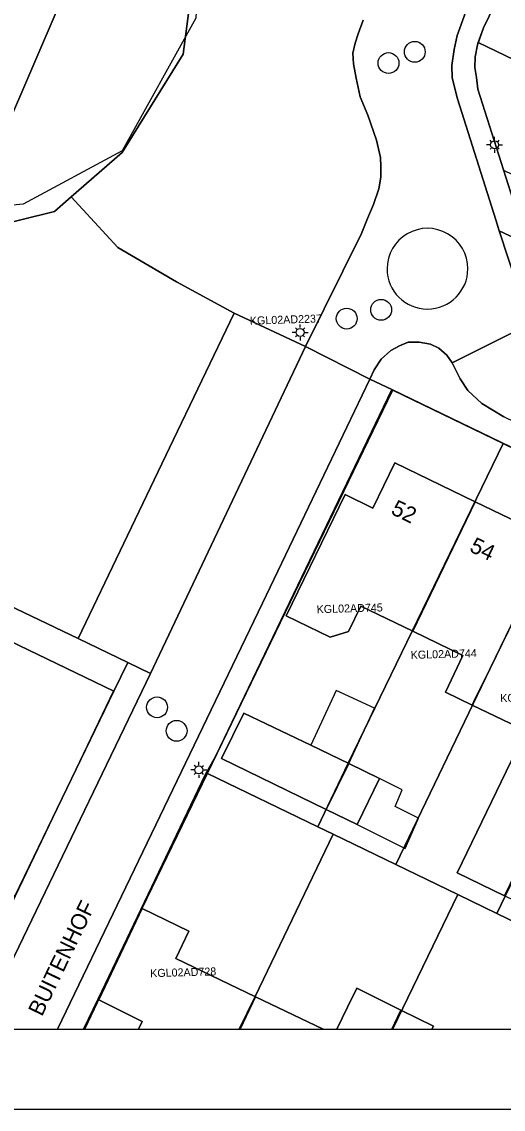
# Model space of a CAD drawing. Extents: x 124901 to 125496, y 515369 to 515789.
# Drawn here: x 125140.8 to 125170.8, y 515368.5 to 515436.5 of the extents above; entities that cross this region are included whole.
import ezdxf

# ---------------------------------------------------------------- set-up
doc = ezdxf.new("R2010")
doc.units = 0
for name, color, linetype in [('Alg Kaders', 7, 'Continuous'), ('Gebouw', 7, 'Continuous'), ('Lichtmast', 7, 'Continuous'), ('Luifel', 7, 'Continuous'), ('Onbegroeid terrein', 7, 'Continuous'), ('Parkeren', 7, 'Continuous'), ('Perceelnummers', 7, 'Continuous'), ('Perceelsgrenzen', 7, 'Continuous'), ('Putten', 7, 'Continuous'), ('Scheiding', 7, 'Continuous'), ('Teksten', 7, 'Continuous'), ('Vegetatie', 7, 'Continuous'), ('Voetpad', 7, 'Continuous'), ('Wegen drempel verkeerseiland', 7, 'Continuous'), ('Wegen lokale weg', 7, 'Continuous')]:
    doc.layers.add(name, color=color, linetype=linetype)

msp = doc.modelspace()

# ---------------------------------------------------------------- linework, layer by layer
at = {"layer": 'Alg Kaders'}
for points in [[(125495.925, 515789.043), (124901.425, 515789.043), (124901.425, 515368.543), (125495.925, 515368.543)], [(125490.925, 515784.043), (124906.425, 515784.043), (124906.425, 515373.543), (125490.925, 515373.543)]]:
    msp.add_lwpolyline(points, close=True, dxfattribs=at)
at = {"layer": 'Gebouw'}
for points in [[(125165.169, 515398.421), (125169.07, 515406.51), (125164.06, 515408.94), (125162.687, 515406.107), (125160.95, 515406.949), (125157.276, 515399.368), (125160.016, 515398.044), (125161.16, 515398.388), (125161.933, 515399.984)], [(125169.097, 515394.251), (125170.01, 515396.08), (125173.916, 515404.167), (125169.07, 515406.51), (125165.169, 515398.421), (125168.31, 515396.902), (125167.227, 515394.6), (125168.881, 515393.801)], [(125175.327, 515391.013), (125174.048, 515391.631), (125178.94, 515401.74), (125173.916, 515404.167), (125170.01, 515396.08), (125169.097, 515394.251), (125168.881, 515393.801), (125172.231, 515392.183), (125167.946, 515383.314), (125170.907, 515381.883), (125172.302, 515384.763), (125173.048, 515386.304)], [(125153.227, 515390.452), (125159.76, 515387.27), (125161.177, 515390.143), (125158.809, 515391.285), (125154.627, 515393.303)], [(125159.76, 515387.27), (125161.7, 515386.34), (125163.09, 515389.22), (125161.177, 515390.143)]]:
    msp.add_lwpolyline(points, close=True, dxfattribs=at)
for points in [[(125154.406, 515373.543), (125155.363, 515375.574), (125150.38, 515377.97), (125151.2, 515379.68), (125148.29, 515381.08), (125145.58, 515375.39), (125148.29, 515374.02), (125148.06, 515373.543)], [(125163.874, 515373.543), (125164.439, 515374.743), (125161.678, 515376.107), (125161.11, 515374.93), (125160.441, 515373.543)], [(125159.587, 515373.543), (125155.363, 515375.574), (125154.406, 515373.543)], [(125166.368, 515373.543), (125166.468, 515373.74), (125164.439, 515374.743), (125163.874, 515373.543)]]:
    msp.add_lwpolyline(points, dxfattribs=at)
at = {"layer": 'Lichtmast'}
for p, q in [((125169.984, 515428.814), (125169.784, 515428.813)), ((125170.072, 515429.025), (125170.002, 515429.096)), ((125170.284, 515429.113), (125170.284, 515429.313)), ((125170.496, 515429.025), (125170.567, 515429.097)), ((125170.584, 515428.813), (125170.784, 515428.813)), ((125170.072, 515428.601), (125170, 515428.53)), ((125170.284, 515428.513), (125170.284, 515428.313)), ((125170.496, 515428.601), (125170.566, 515428.53)), ((125157.931, 515417.3), (125157.861, 515417.371)), ((125158.143, 515417.388), (125158.143, 515417.588)), ((125158.355, 515417.3), (125158.426, 515417.372)), ((125157.843, 515417.089), (125157.643, 515417.088)), ((125157.931, 515416.876), (125157.859, 515416.805)), ((125158.143, 515416.788), (125158.143, 515416.588)), ((125158.355, 515416.876), (125158.425, 515416.805)), ((125158.443, 515417.088), (125158.643, 515417.088)), ((125151.817, 515390.048), (125151.817, 515390.248)), ((125151.517, 515389.749), (125151.317, 515389.748)), ((125151.605, 515389.536), (125151.533, 515389.465)), ((125151.605, 515389.96), (125151.535, 515390.031)), ((125151.817, 515389.448), (125151.817, 515389.248)), ((125152.029, 515389.96), (125152.1, 515390.032)), ((125152.029, 515389.536), (125152.099, 515389.465)), ((125152.117, 515389.748), (125152.317, 515389.748))]:
    msp.add_line(p, q, dxfattribs=at)
for centre in [(125170.284, 515428.813), (125158.143, 515417.088), (125151.817, 515389.748)]:
    msp.add_circle(centre, 0.25, dxfattribs=at)
at = {"layer": 'Luifel'}
for points in [[(125158.809, 515391.285), (125161.177, 515390.143), (125162.786, 515393.605), (125160.402, 515394.712)], [(125161.7, 515386.34), (125164.705, 515384.841), (125165.536, 515386.737), (125164.07, 515387.456), (125164.516, 515388.502), (125163.09, 515389.22)]]:
    msp.add_lwpolyline(points, close=True, dxfattribs=at)
at = {"layer": 'Onbegroeid terrein'}
for points in [[(125095.075, 515423.399), (125099.204, 515432.322), (125110.655, 515427.43), (125122.127, 515422.267), (125130.143, 515418.768), (125132.577, 515423.948), (125138.495, 515423.574), (125142.807, 515424.652), (125143.845, 515425.555), (125147.032, 515428.328), (125150.834, 515434.472), (125151.815, 515441.972), (125155.511, 515449.984), (125159.029, 515454.001), (125160.437, 515457.237), (125161.603, 515461.705), (125161.995, 515465.762), (125161.709, 515471.904), (125160.588, 515478.821), (125154.166, 515482.121), (125107.13, 515506.248), (125106.866, 515505.735), (125103.421, 515507.503), (125097.735, 515510.333)], [(125183.072, 515404.238), (125163.857, 515413.516), (125152.878, 515390.622), (125152.215, 515389.431), (125145.53, 515375.452), (125144.611, 515373.543)], [(125136.331, 515373.543), (125137.384, 515375.767), (125146.51, 515394.675), (125137, 515399.26), (125135.58, 515396.36), (125129.94, 515399.1), (125131.35, 515401.99), (125125.487, 515404.755), (125124.13, 515401.923), (125118.359, 515389.883), (125117.867, 515388.856), (125116.219, 515385.842), (125115.753, 515384.991), (125084.319, 515400.267)], [(125148.06, 515373.543), (125148.29, 515374.02), (125145.58, 515375.39), (125148.29, 515381.08), (125151.2, 515379.68), (125150.38, 515377.97), (125155.363, 515375.574), (125159.587, 515373.543)], [(125160.441, 515373.543), (125161.11, 515374.93), (125161.678, 515376.107), (125164.439, 515374.743), (125166.468, 515373.74), (125166.368, 515373.543)]]:
    msp.add_lwpolyline(points, dxfattribs=at)
for points in [[(125212.378, 515407.217), (125218.773, 515420.602), (125228.705, 515441.027), (125231.369, 515446.506), (125208.757, 515457.227), (125207.246, 515457.999), (125185.331, 515468.649), (125174.743, 515446.788), (125169.594, 515436.119), (125169.208, 515435.054), (125169.078, 515434.302), (125169.052, 515433.637), (125169.143, 515433.015), (125169.246, 515432.293), (125171.72, 515424.504), (125175.501, 515422.7), (125184.563, 515418.371), (125187.6, 515416.92), (125188.955, 515416.229), (125189.83, 515418.039), (125192.711, 515416.656), (125201.09, 515412.635)], [(125174.048, 515391.631), (125175.327, 515391.013), (125173.048, 515386.304), (125172.302, 515384.763), (125174.28, 515383.82), (125172.88, 515380.93), (125170.907, 515381.883), (125167.946, 515383.314), (125172.231, 515392.183), (125168.881, 515393.801), (125167.227, 515394.6), (125168.31, 515396.902), (125165.169, 515398.421), (125161.933, 515399.984), (125161.16, 515398.388), (125160.016, 515398.044), (125157.276, 515399.368), (125160.95, 515406.949), (125162.687, 515406.107), (125164.06, 515408.94), (125169.07, 515406.51), (125173.916, 515404.167), (125178.94, 515401.74)], [(125161.7, 515386.34), (125159.76, 515387.27), (125153.227, 515390.452), (125154.627, 515393.303), (125158.809, 515391.285), (125161.177, 515390.143), (125163.09, 515389.22)]]:
    msp.add_lwpolyline(points, close=True, dxfattribs=at)
at = {"layer": 'Parkeren'}
msp.add_lwpolyline([(125147.377, 515396.464), (125148.792, 515395.778), (125158.481, 515416.215), (125154.025, 515418.282), (125149.995, 515409.883), (125144.277, 515397.967)], close=True, dxfattribs=at)
at = {"layer": 'Perceelsgrenzen'}
for points in [[(125180.365, 515504.659), (125162.009, 515468.834), (125162.385, 515467.065), (125162.267, 515459.869), (125159.338, 515453.361), (125153.997, 515447.989), (125151.969, 515443.01), (125151.625, 515436.721), (125147.022, 515428.44), (125140.851, 515425.095), (125137.489, 515424.795), (125136.248, 515422.103), (125133.299, 515423.571), (125132.648, 515423.861), (125129.798, 515417.933), (125127.09, 515412.3), (125123.6, 515405.04), (125120.86, 515399.36), (125116.204, 515389.664), (125108.472, 515393.42), (125100.776, 515397.159), (125093.068, 515400.904)], [(125096.909, 515494.22), (125104.802, 515490.703), (125113.746, 515486.742), (125122.47, 515482.934), (125130.175, 515479.614), (125138.626, 515475.74), (125146.681, 515472.032), (125153.276, 515469.016), (125156.614, 515467.536), (125154.859, 515463.81), (125150.814, 515455.066), (125146.958, 515446.252), (125143.158, 515437.682), (125139.694, 515429.575), (125137.489, 515424.795), (125136.248, 515422.103), (125133.299, 515423.571), (125132.648, 515423.861), (125120.613, 515429.23), (125108.933, 515434.353), (125097.173, 515439.469)], [(125170.86, 515427.213), (125169.246, 515432.293), (125169.143, 515433.015), (125169.052, 515433.637), (125169.078, 515434.302), (125169.208, 515435.054), (125169.26, 515435.197), (125169.594, 515436.119), (125171.391, 515439.843)], [(125144.701, 515373.543), (125148.29, 515381.08), (125152.36, 515389.52), (125163.92, 515413.47), (125170.82, 515410.14), (125175.68, 515407.78), (125181.99, 515404.72), (125188.32, 515401.65), (125193.17, 515399.3), (125198.03, 515396.95), (125206.918, 515392.721), (125212.367, 515390.098), (125213.094, 515389.625), (125213.365, 515389.379), (125213.79, 515388.801), (125214.355, 515387.779), (125214.411, 515387.637), (125214.641, 515387.049), (125214.793, 515386.288), (125214.802, 515385.563), (125214.687, 515385.058), (125211.738, 515378.87), (125209.948, 515375.113), (125209.186, 515373.543)], [(125098.86, 515393.2), (125106.56, 515389.49), (125112.92, 515386.42), (125113.8, 515385.99), (125115.97, 515384.95), (125116.36, 515385.77), (125119.36, 515391.96), (125125.54, 515404.8), (125137, 515399.26), (125146.5, 515394.68), (125140.36, 515381.86), (125137.384, 515375.767), (125136.63, 515374.174), (125136.331, 515373.543)], [(125144.701, 515373.543), (125148.29, 515381.08), (125152.36, 515389.52), (125159.24, 515386.19), (125160.2, 515385.73), (125155.33, 515375.59), (125154.331, 515373.543)], [(125154.331, 515373.543), (125155.33, 515375.59), (125160.2, 515385.73), (125164.11, 515383.84), (125167.98, 515381.96), (125163.94, 515373.56), (125163.932, 515373.543)], [(125163.932, 515373.543), (125163.94, 515373.56), (125167.98, 515381.96), (125170.43, 515380.78), (125175.76, 515378.2), (125173.519, 515373.543)]]:
    msp.add_lwpolyline(points, dxfattribs=at)
for points in [[(125137.489, 515424.795), (125139.694, 515429.575), (125143.158, 515437.682), (125146.958, 515446.252), (125150.814, 515455.066), (125154.859, 515463.81), (125156.614, 515467.536), (125158.866, 515466.538), (125160.498, 515465.884), (125162.009, 515468.834), (125162.385, 515467.065), (125162.267, 515459.869), (125159.338, 515453.361), (125153.997, 515447.989), (125151.969, 515443.01), (125151.625, 515436.721), (125147.022, 515428.44), (125140.851, 515425.095)], [(125171.391, 515439.843), (125184.28, 515433.63), (125194.19, 515428.85), (125191.98, 515424.25), (125182.06, 515429.04), (125169.26, 515435.197), (125169.594, 515436.119)], [(125188.269, 515418.797), (125170.86, 515427.213), (125169.246, 515432.293), (125169.143, 515433.015), (125169.052, 515433.637), (125169.078, 515434.302), (125169.208, 515435.054), (125169.26, 515435.197), (125182.06, 515429.04), (125191.98, 515424.25), (125189.14, 515418.37)], [(125159.24, 515386.19), (125152.36, 515389.52), (125163.92, 515413.47), (125170.82, 515410.14), (125161.15, 515390.16)], [(125175.68, 515407.78), (125170.001, 515396.085), (125164.11, 515383.84), (125160.2, 515385.73), (125159.24, 515386.19), (125161.15, 515390.16), (125170.82, 515410.14)], [(125164.11, 515383.84), (125170.001, 515396.085), (125175.68, 515407.78), (125181.99, 515404.72), (125172.33, 515384.75), (125170.43, 515380.78), (125167.98, 515381.96)], [(125119.36, 515391.96), (125125.54, 515404.8), (125137, 515399.26), (125146.5, 515394.68), (125140.36, 515381.86), (125129.4, 515387.12)], [(125170.43, 515380.78), (125172.33, 515384.75), (125181.99, 515404.72), (125188.32, 515401.65), (125183.52, 515391.76), (125176.75, 515377.73), (125175.76, 515378.2)]]:
    msp.add_lwpolyline(points, close=True, dxfattribs=at)
at = {"layer": 'Putten'}
for centre in [(125165.3, 515434.62), (125163.66, 515433.92), (125163.2, 515418.5), (125161.05, 515417.95), (125149.21, 515393.66), (125150.43, 515392.19)]:
    msp.add_circle(centre, 0.65, dxfattribs=at)
at = {"layer": 'Scheiding'}
msp.add_lwpolyline([(125152.878, 515390.622), (125152.215, 515389.431)], dxfattribs=at)
at = {"layer": 'Vegetatie'}
msp.add_lwpolyline([(125151.815, 515441.972), (125150.834, 515434.472), (125147.032, 515428.328), (125143.845, 515425.555), (125146.751, 515422.394), (125150.418, 515420.241), (125154.025, 515418.282), (125158.481, 515416.215), (125161.964, 515423.265), (125162.353, 515424.215), (125162.729, 515425.079), (125163.06, 515426.064), (125163.188, 515426.782), (125163.183, 515427.453), (125163.165, 515428.025), (125162.917, 515429.094), (125162.36, 515430.661), (125161.886, 515431.81), (125161.632, 515432.976), (125161.484, 515433.864), (125161.44, 515434.539), (125161.576, 515435.164), (125161.765, 515435.74), (125162.08, 515436.601)], dxfattribs=at)
for points in [[(125146.751, 515422.394), (125143.845, 515425.555), (125142.807, 515424.652), (125138.495, 515423.574), (125132.577, 515423.948), (125130.143, 515418.768), (125124.633, 515407.369), (125126.314, 515406.564), (125144.277, 515397.967), (125149.995, 515409.883), (125154.025, 515418.282), (125150.418, 515420.241)], [(125177.662, 515420.098), (125174.885, 515421.409), (125170.572, 515423.444), (125171.736, 515419.886), (125172.038, 515418.969), (125172.431, 515418.264), (125172.788, 515417.761), (125172.884, 515417.626), (125173.484, 515417.034), (125174.336, 515416.354), (125175.453, 515415.748)]]:
    msp.add_lwpolyline(points, close=True, dxfattribs=at)
at = {"layer": 'Voetpad'}
for points in [[(125167.769, 515434.757), (125167.61, 515433.758), (125167.642, 515432.996), (125167.965, 515431.692), (125170.351, 515424.118), (125170.572, 515423.444), (125174.885, 515421.409), (125175.501, 515422.7), (125171.72, 515424.504), (125169.246, 515432.293), (125169.143, 515433.015), (125169.052, 515433.637), (125169.078, 515434.302), (125169.208, 515435.054), (125169.594, 515436.119), (125174.743, 515446.788), (125185.331, 515468.649), (125184.024, 515469.175), (125173.585, 515447.618), (125168.466, 515437.087), (125167.943, 515435.636)], [(125163.857, 515413.516), (125183.072, 515404.238), (125203.044, 515394.519), (125205.837, 515393.241), (125210.536, 515390.979), (125211.161, 515392.277), (125191.147, 515402.019), (125173.004, 515410.774), (125170.868, 515411.802), (125169.485, 515412.635), (125168.607, 515413.459), (125168.133, 515414.185), (125167.628, 515415.179), (125167.31, 515415.656), (125166.81, 515416.11), (125166.278, 515416.36), (125165.583, 515416.487), (125164.88, 515416.468), (125164.339, 515416.259), (125163.813, 515415.96), (125163.197, 515415.41), (125162.769, 515414.755), (125162.489, 515414.171)], [(125131.35, 515401.99), (125137, 515399.26), (125146.51, 515394.675), (125147.377, 515396.464), (125144.277, 515397.967), (125126.314, 515406.564), (125124.633, 515407.369), (125123.6, 515405.04), (125120.86, 515399.36), (125115.972, 515389.777), (125117.867, 515388.856), (125118.359, 515389.883), (125124.13, 515401.923), (125125.487, 515404.755)]]:
    msp.add_lwpolyline(points, close=True, dxfattribs=at)
for points in [[(125144.611, 515373.543), (125145.53, 515375.452), (125152.215, 515389.431), (125152.878, 515390.622), (125163.857, 515413.516), (125162.489, 515414.171), (125155.786, 515400.175), (125143.001, 515373.543)], [(125138.082, 515373.543), (125141.121, 515379.815), (125148.792, 515395.778), (125147.377, 515396.464), (125146.51, 515394.675), (125137.384, 515375.767), (125136.331, 515373.543)]]:
    msp.add_lwpolyline(points, dxfattribs=at)
at = {"layer": 'Wegen drempel verkeerseiland'}
for start, end in [(359.98864, 180.01136), (180.01136, 359.98864)]:
    msp.add_arc((125166.09, 515421.069), 2.523, start, end, dxfattribs=at)
at = {"layer": 'Wegen lokale weg'}
for points in [[(125171.736, 515419.886), (125170.572, 515423.444), (125170.351, 515424.118), (125167.965, 515431.692), (125167.642, 515432.996), (125167.61, 515433.758), (125167.769, 515434.757), (125167.943, 515435.636), (125168.466, 515437.087), (125173.585, 515447.618)], [(125162.08, 515436.601), (125161.765, 515435.74), (125161.576, 515435.164), (125161.44, 515434.539), (125161.484, 515433.864), (125161.632, 515432.976), (125161.886, 515431.81), (125162.36, 515430.661), (125162.917, 515429.094), (125163.165, 515428.025), (125163.183, 515427.453), (125163.188, 515426.782), (125163.06, 515426.064), (125162.729, 515425.079), (125162.353, 515424.215), (125161.964, 515423.265), (125158.481, 515416.215), (125162.489, 515414.171), (125162.769, 515414.755), (125163.197, 515415.41), (125163.813, 515415.96), (125164.339, 515416.259), (125164.88, 515416.468), (125165.583, 515416.487), (125166.278, 515416.36), (125166.81, 515416.11), (125167.31, 515415.656), (125167.628, 515415.179), (125172.788, 515417.761)], [(125172.788, 515417.761), (125167.628, 515415.179), (125168.133, 515414.185), (125168.607, 515413.459), (125169.485, 515412.635), (125170.868, 515411.802)], [(125143.001, 515373.543), (125155.786, 515400.175), (125162.489, 515414.171), (125158.481, 515416.215), (125148.792, 515395.778), (125141.121, 515379.815), (125138.082, 515373.543)]]:
    msp.add_lwpolyline(points, dxfattribs=at)
for start, end in [(359.98864, 180.01136), (180.01136, 359.98864)]:
    msp.add_arc((125166.09, 515421.069), 2.523, start, end, dxfattribs=at)

# ---------------------------------------------------------------- texts
at = {"layer": 'Perceelnummers'}
for s, rotation, p in [('KGL02AD2237', 1.82985, (125155.012, 515417.569)), ('KGL02AD745', 1.63171, (125159.181, 515399.537)), ('KGL02AD744', 1.63178, (125165.051, 515396.682)), ('KGL02AD743', 1.63185, (125170.641, 515393.982)), ('KGL02AD728', 1.63159, (125148.787, 515376.793))]:
    msp.add_text(s, height=0.5, rotation=rotation, dxfattribs=at).set_placement(p)
at = {"layer": 'Teksten'}
for s, rotation, p in [('52', 334.1, (125163.751, 515405.769)), ('54', 334.2, (125168.654, 515403.43)), ('BUITENHOF', 64.3, (125142.021, 515374.295))]:
    msp.add_text(s, height=1, rotation=rotation, dxfattribs=at).set_placement(p)

doc.saveas('drawing.dxf')
